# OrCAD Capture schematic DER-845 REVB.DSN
size B; title: DER 845 16V 0.3A LNK-TN2-900; rev: B
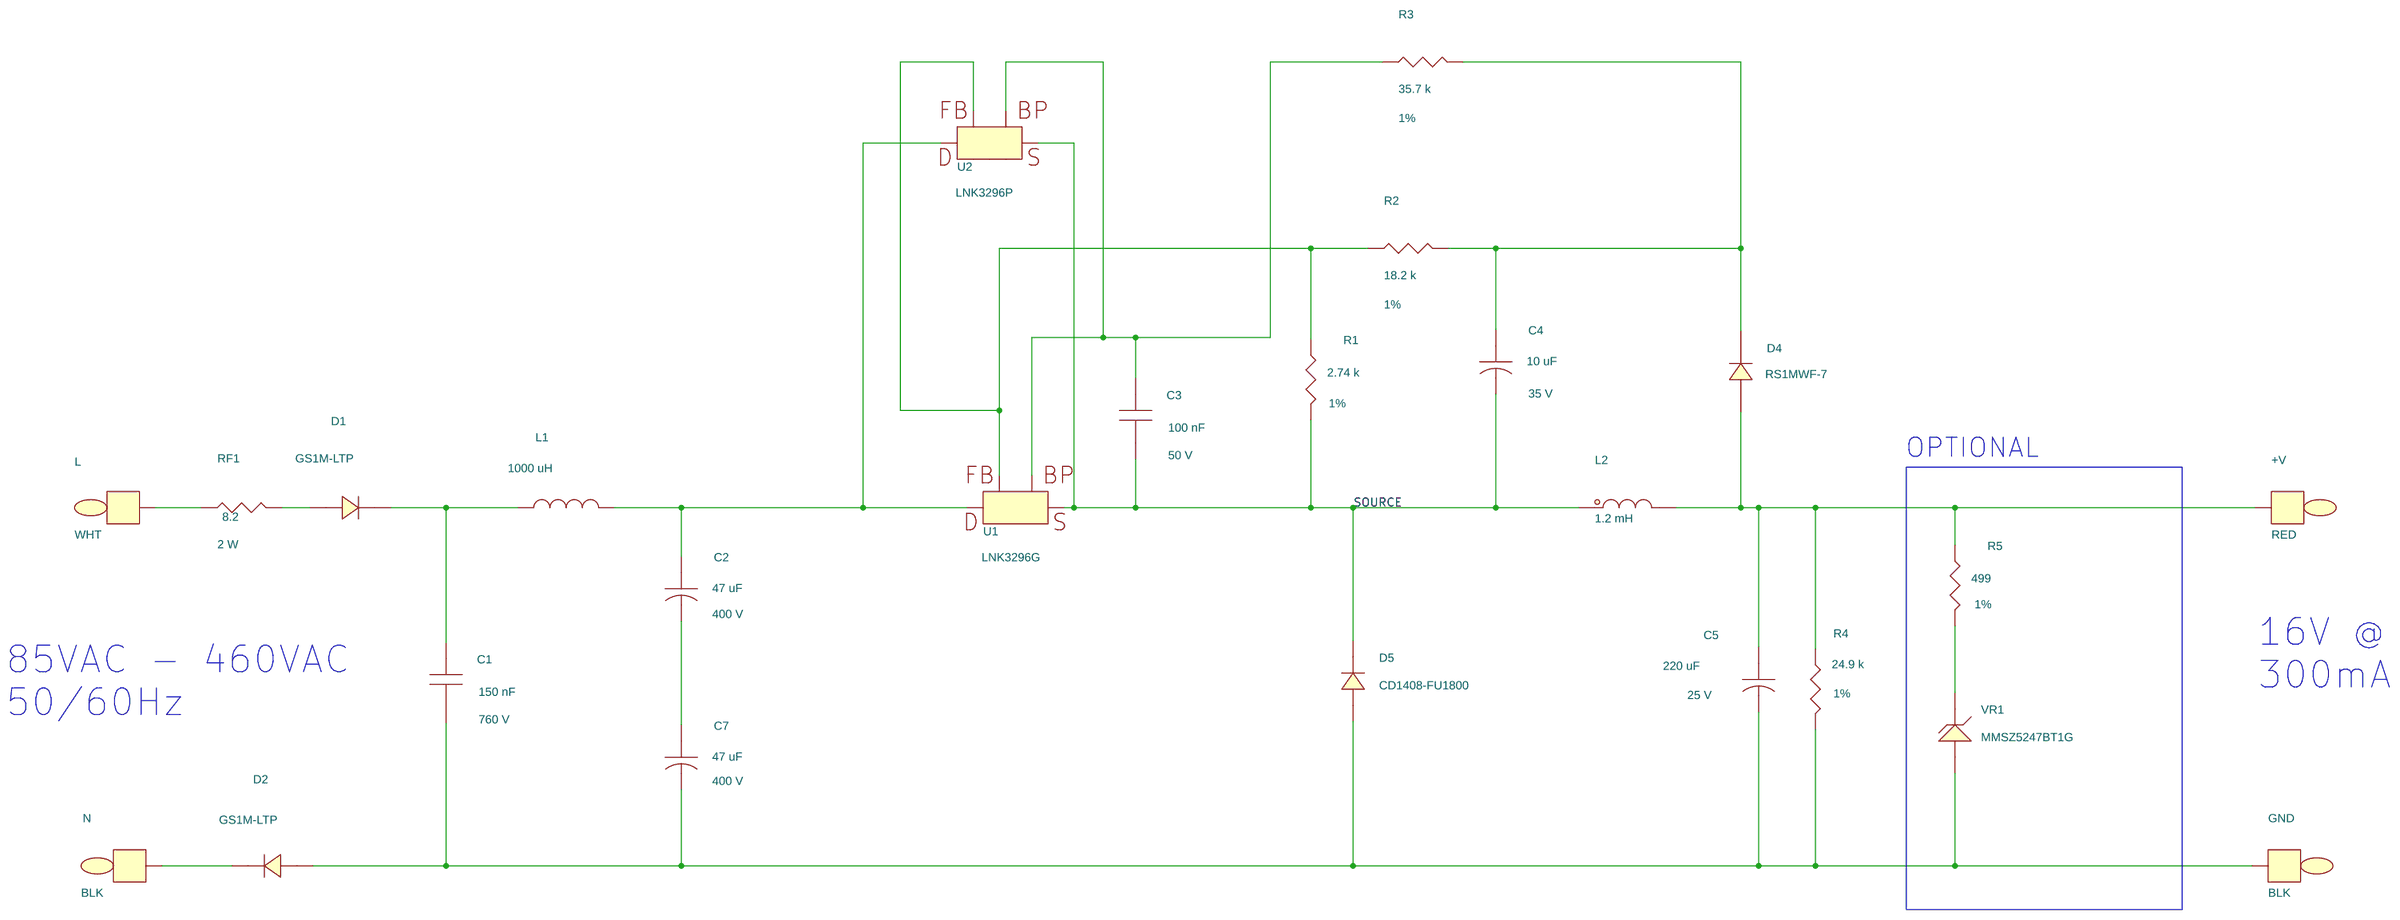
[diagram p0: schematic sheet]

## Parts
+V  RED  [pitpkeystone100x100]
C1  150 nF  [pi_np_caprad709x276ls590d050]
C2  47 uF  [pipolcapclyd500ls200040]
C3  100 nF  [pismc0805]
C4  10 uF  [pipolcapclyd200ls80030]
C5  220 uF  [pipolcapclyd320ls140030]
C7  47 uF  [pipolcapclyd500ls200040]
D1  GS1M-LTP  [pismdo214ac12]
D2  GS1M-LTP  [pismdo214ac12]
D4  RS1MWF-7  [pi_sm_sod-123_12]
D5  CD1408-FU1800  [pismd1408]
GND  BLK  [pitpkeystone100x100]
L  WHT  [pitpkeystone125x125]
L1  1000 uH  [pichoketokinvd216h413ls098d030]
L2  1.2 mH  [pi_choke_RL5480-3_d2]
N  BLK  [pitpkeystone125x125]
R1  2.74 k  [pismr0603]
R2  18.2 k  [pismr0603]
R3  35.7 k  [pismr0805]
R4  24.9 k  [pismr0805]
R5  499  [pismr0603]
RF1  8.2  [pi2wresd200ls725d040]
U1  LNK3296G  [piicsmd8cshort5678ipc]
U2  LNK3296P  [piicdip8cshort5678]
VR1  MMSZ5247BT1G  [pi_sm_sod-123_12]

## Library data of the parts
+V = TESTPOINT: Part Number: 35-00080-00
C1 = CAP_NP: Disp_Voltage: 760 V; Part Number: 20-01058-00; Voltage: 760 V
C2 C7 = CAP_POL: ALT_SYMBOLS: pipolcapclyd500ls2000401200lh; Disp_Voltage: 400 V; FPLIST: pipolcapclyd500ls200040,pipolcapclyd500ls2000401200lh; Part Number: 20-00883-00; Voltage: 400 V
C3 = CAP_NP: Disp_Voltage: 50 V; Part Number: 20-00904-00; Voltage: 50 V
C4 = CAP_POL: ALT_SYMBOLS: pipolcapclyd200ls80030h; Disp_Voltage: 35 V; FPLIST: pipolcapclyd200ls80030,pipolcapclyd200ls80030h; Part Number: 20-01007-00; Voltage: 35 V
C5 = CAP_POL: ALT_SYMBOLS: pipolcapclyd320ls140030430h; Disp_Voltage: 25 V; FPLIST: pipolcapclyd320ls140030,pipolcapclyd320ls140030430h; Part Number: 20-00028-00; Voltage: 25 V
D1 D2 = DIODE: Part Number: 15-01111-00
D4 = DIODE: ALT_SYMBOLS: pi_sm_sod-123_12_1; FPLIST: pi_sm_sod-123_12,pi_sm_sod-123_12_1; Part Number: 15-01214-00
D5 = DIODE: Part Number: 15-01580-00
GND = TESTPOINT: Part Number: 35-00079-00
L = TESTPOINT: Part Number: 35-00044-00
L1 = INDUCTOR: Part Number: 30-00020-00
L2 = INDUCTOR_DOT2: ALT_SYMBOLS: pi_choke_RL5480-3H_d2; FPLIST: pi_choke_RL5480-3_d2,pi_choke_RL5480-3H_d2; Part Number: 30-00430-00
N = TESTPOINT: Part Number: 35-00042-00
R1 = R: Disp_Tol: 1%; Part Number: 05-01120-00
R2 = R: Disp_Tol: 1%; Part Number: 05-03209-00
R3 = R: Disp_Tol: 1%; Part Number: 05-00737-00
R4 = R: Disp_Tol: 1%; Part Number: 05-00722-00
R5 = R: Disp_Tol: 1%; Part Number: 05-01049-00
RF1 = RF: ALT_SYMBOLS: pi2wresd200ls900d040,pi2wvresd200ls300d040,pi2wvresd200ls400d040,pi2wvresd180ls250d040,pi2wvresd180ls200d040; Disp_Power: 2 W; FPLIST: pi2wresd200ls725d040,pi2wresd200ls900d040,pi2wvresd200ls300d040,pi2wvresd200ls400d040,pi2wvresd180ls250d040,pi2wvresd180ls200d040; Part Number: 05-03076-00
U1 = LNK32XX_8C: ALT_SYMBOLS: piicsmd8cshort5678; FPLIST: piicsmd8cshort5678ipc,piicsmd8cshort5678; Part Number: 10-01103-00
U2 = LNK32XX_8C: Part Number: 10-01102-00
VR1 = DIODE_ZENER: Part Number: 15-01362-00

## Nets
SOURCE: C3.2 C4.2 D5.1 L2.2 R1.2 U1.5(S) U1.6(SOURCE) U1.7(SOURCE) U1.8(SOURCE) U2.5(S) U2.6(SOURCE) U2.7(SOURCE) U2.8(SOURCE)
N109644: C1.1 D1.1 L1.1
N109746: C2.1 L1.2 U1.4(D) U2.4(D)
N109826: C1.2 C5.2 C7.2 D2.2 D5.2 GND.1 R4.2 VR1.2
N110802: C3.1 R3.1 U1.1(BP) U2.1(BP)
N111146: R1.1 R2.1 U1.2(FB) U2.2(FB)
N111959: +V.1 C5.1 D4.2 L2.1 R4.1 R5.1
N118115: D1.2 RF1.2
N118119: L.1 RF1.1
N4132044: C4.1 D4.1 R2.2 R3.2
N4143200: D2.1 N.1
N4148852: C2.2 C7.1
N4178876: R5.2 VR1.1

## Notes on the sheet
- OPTIONAL
- 16V @
  300mA
- 85VAC - 460VAC
  50/60Hz
